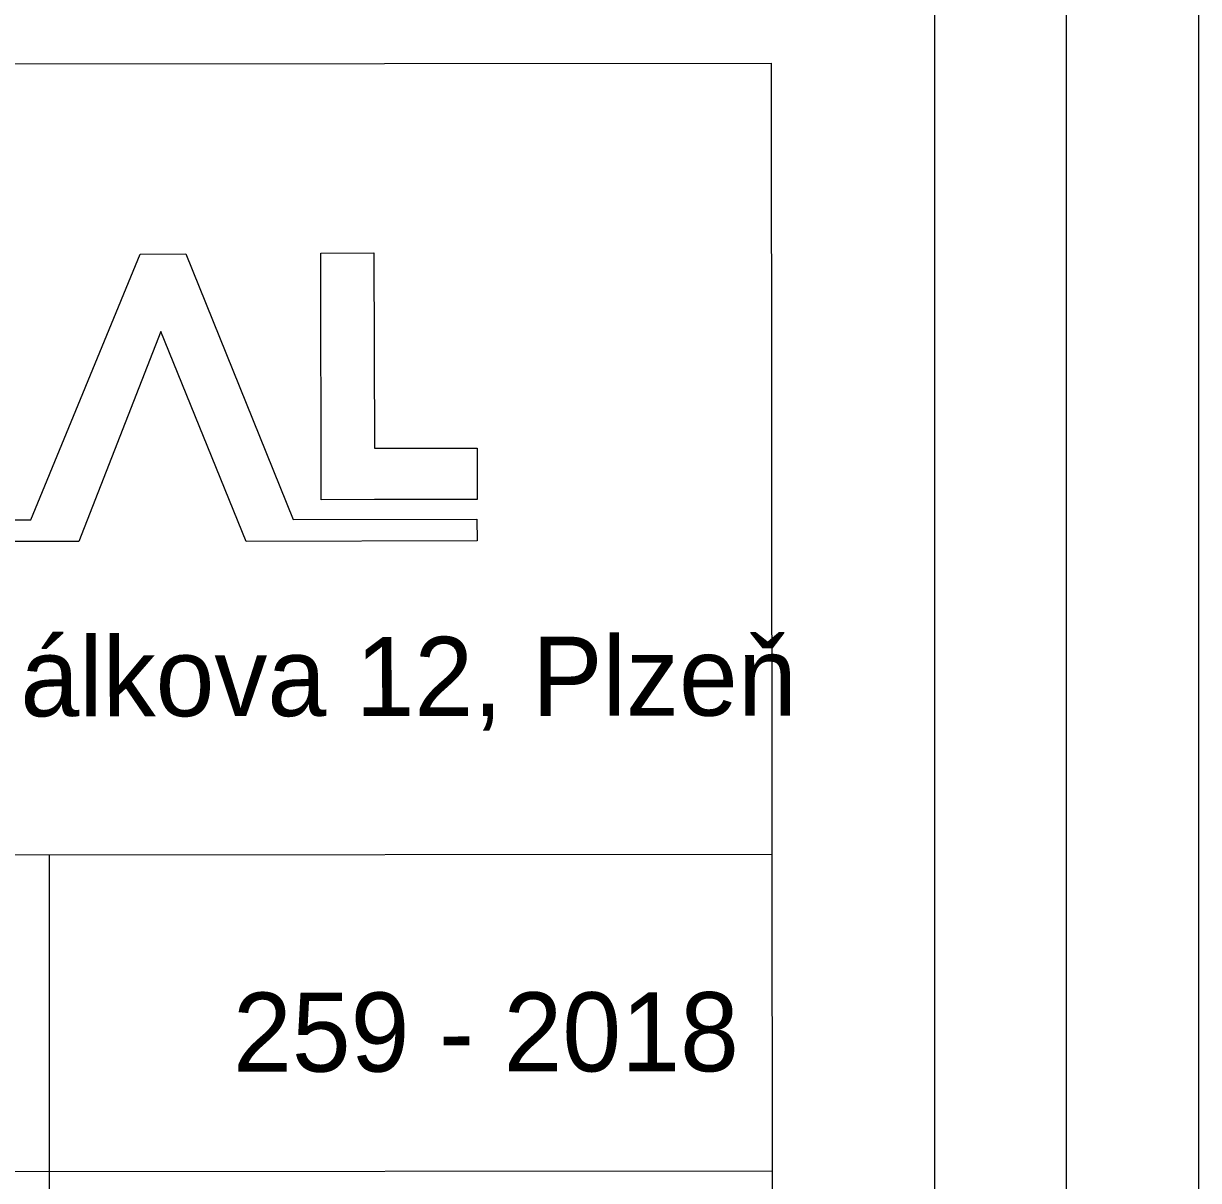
# Model space of a CAD drawing. Extents: x -762531 to -762101, y -1049246 to -1048939.
# Drawn here: x -762145.67 to -762101.11, y -1049195.49 to -1049151.61 of the extents above; entities that cross this region are included whole.
import ezdxf

# ---------------------------------------------------------------- set-up
doc = ezdxf.new("R2010")
doc.units = 0
for name, color, linetype in [('Default', 7, 'Continuous'), ('Rozpiska', 7, 'Continuous'), ('U_formát', 7, 'Continuous'), ('U_rozvržení_rámeček', 7, 'Continuous'), ('Z_Popisky', 7, 'Continuous')]:
    doc.layers.add(name, color=color, linetype=linetype)

# ---------------------------------------------------------------- blocks, each defined once
blk = doc.blocks.new('AnonymousCell-flat-1')
at = {"layer": 'Rozpiska'}
for p, q in [((24.562, 9.252), (26.548, 9.566)), ((24.562, 9.252), (26.548, 9.566)), ((26.548, 9.566), (27.72, 2.26)), ((26.548, 9.566), (27.72, 2.26)), ((26.024, 0.013), (24.562, 9.252)), ((26.024, 0.013), (24.562, 9.252)), ((15.259, -2.441), (17.802, 8.156)), ((15.259, -2.441), (17.802, 8.156)), ((17.802, 8.156), (19.514, 8.427)), ((17.802, 8.156), (19.514, 8.427)), ((19.514, 8.427), (25.091, -0.892)), ((19.514, 8.427), (25.091, -0.892)), ((19.029, 5.382), (17.188, -2.97)), ((19.029, 5.382), (17.188, -2.97)), ((23.455, -1.992), (19.029, 5.382)), ((23.455, -1.992), (19.029, 5.382)), ((27.72, 2.26), (31.566, 2.852)), ((27.72, 2.26), (31.566, 2.852)), ((31.566, 2.852), (31.865, 0.935)), ((31.566, 2.852), (31.865, 0.935)), ((31.865, 0.935), (28.01, 0.327)), ((31.865, 0.935), (28.01, 0.327)), ((25.091, -0.892), (31.958, 0.195)), ((25.091, -0.892), (31.958, 0.195)), ((28.01, 0.327), (26.024, 0.013)), ((28.01, 0.327), (26.024, 0.013)), ((31.958, 0.195), (32.108, -0.616)), ((31.958, 0.195), (32.108, -0.616)), ((32.108, -0.616), (23.455, -1.992)), ((32.108, -0.616), (23.455, -1.992)), ((-30.481, -9.671), (15.259, -2.441)), ((-30.481, -9.671), (15.259, -2.441)), ((17.188, -2.97), (-30.357, -10.494)), ((17.188, -2.97), (-30.357, -10.494))]:
    blk.add_line(p, q, dxfattribs=at)
for points in [[(24.562, 9.252), (26.548, 9.566), (27.72, 2.26), (31.566, 2.852), (31.865, 0.935), (28.01, 0.327), (26.024, 0.013), (24.562, 9.252)], [(24.562, 9.252), (26.548, 9.566), (27.72, 2.26), (31.566, 2.852), (31.865, 0.935), (28.01, 0.327), (26.024, 0.013), (24.562, 9.252)], [(17.802, 8.156), (19.514, 8.427), (25.091, -0.892), (31.958, 0.195), (32.108, -0.616), (23.455, -1.992), (19.029, 5.382), (17.188, -2.97), (-30.357, -10.494), (-30.481, -9.671), (15.259, -2.441), (17.802, 8.156)], [(17.802, 8.156), (19.514, 8.427), (25.091, -0.892), (31.958, 0.195), (32.108, -0.616), (23.455, -1.992), (19.029, 5.382), (17.188, -2.97), (-30.357, -10.494), (-30.481, -9.671), (15.259, -2.441), (17.802, 8.156)]]:
    blk.add_lwpolyline(points, dxfattribs=at)
blk = doc.blocks.new('U1096')
at = {"layer": 'Default'}
blk.add_lwpolyline([(0, -297), (0, 0), (-420, 0), (-420, -297)], close=True, dxfattribs=at)
at = {"layer": 'U_formát'}
for points in [[(-425, 5), (5, 5), (5, -302), (-425, -302)], [(-5, -292), (-5, -5), (-415, -5), (-415, -292)]]:
    blk.add_lwpolyline(points, close=True, dxfattribs=at)

msp = doc.modelspace()

# ---------------------------------------------------------------- linework, layer by layer
at = {"layer": 'Rozpiska'}
for p, q in [((-762290.85, -1049153.279), (-762117.302, -1049153.115)), ((-762290.302, -1049153.279), (-762117.302, -1049153.115)), ((-762117.228, -1049231.115), (-762117.302, -1049153.115)), ((-762117.228, -1049231.115), (-762117.302, -1049153.115)), ((-762290.822, -1049183.279), (-762117.273, -1049183.115)), ((-762290.273, -1049183.279), (-762117.273, -1049183.115)), ((-762144.701, -1049183.141), (-762144.671, -1049231.141)), ((-762144.701, -1049183.141), (-762144.671, -1049231.141)), ((-762165.771, -1049195.161), (-762117.262, -1049195.115)), ((-762165.771, -1049195.161), (-762117.262, -1049195.115))]:
    msp.add_line(p, q, dxfattribs=at)

# ---------------------------------------------------------------- block references
at = {"layer": 'U_rozvržení_rámeček'}
msp.add_blockref('U1096', (-762106.113, -1048944.389), dxfattribs=at)
at = {"layer": 'Z_Popisky', "rotation": -8.873281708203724}
msp.add_blockref('AnonymousCell-flat-1', (-762160.09, -1049165.668), dxfattribs=at)

# ---------------------------------------------------------------- texts
at = {"layer": 'Rozpiska'}
for s, p in [('GEOREAL spol. s r.o., Hálkova 12, Plzeň', (-762189.929, -1049177.927)), ('259 - 2018', (-762137.724, -1049191.363))]:
    msp.add_text(s, height=3, rotation=0.0542, dxfattribs=at).set_placement(p)

doc.saveas('drawing.dxf')
